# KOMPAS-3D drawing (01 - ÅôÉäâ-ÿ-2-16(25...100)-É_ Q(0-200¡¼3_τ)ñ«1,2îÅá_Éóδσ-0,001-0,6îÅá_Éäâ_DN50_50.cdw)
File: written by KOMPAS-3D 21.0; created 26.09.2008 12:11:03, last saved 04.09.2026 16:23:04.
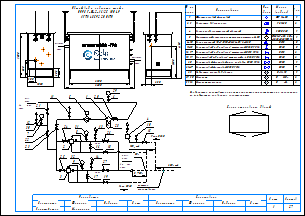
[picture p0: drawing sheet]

Sheets 1-2: A3, landscape

Document properties: Наименование: Макро:21; Автор: RaskoAdmin; Форматы листов документа: 2xA3; Полное имя файла: \\ur38nt01\Departments\КТО\КБ ПУРДГ\Заявки\Прайс-лист на типовые шкафы ГРПШ\ПУРДГ_стандарт_30_04_2026\ПУРДГ с РДГ(Н, В)\ПУРДГ-Ш-2-16(25...100)-Р_ Q(0-200нм3_ч)до1,2МПа_Рвых-0,001-0,6МПа_РДГ_DN50_50.cdw

Title block, sheet 1: Наименование: Пункт учета газа / ПУГ-Ш-400-Р / ЛГТИ.485922.001ТУ; designation: ЛГТИ.03.4411141; sheet number: 1; Количество листов документа: 2; organisation: ООО "ЭЛЬСТЕР Газэлектроника"; Форматы листов документа: A3; stored path: C:\Рабочие документы\Компас\ПУГ\Схема.cdw; Разработал: Устинов; Проверил: Кошкин; Утвердил: Кошкин
Title block, sheet 2: sheet number: 2; stored path: D:\Рабочие документы\Заявки\ПУРДГ\ПУРДГ-ШУЭО-2-100-Р 4411220.cdw; designation, second copy: ЛГТИ.03.4411141-

Views: Вид 1, Вид 2
Referenced files: wcvoit.frw
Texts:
  Normal
  № на
  схеме
  Усл.
  обозн.
  Марка
  (модель)
  Кол.
  Фильтр газовый фланцевый
  ФГ 16-50
  Регулятор давления газа
  РДГ-50
  Клапан предохранительный сбросной
  КПС DN20
  Измерительный комплекс с ротационным счетчиком Ду50
  СГ-ЭК-Р-(0,2...2,0)-
  Кран кнопочный VE-РАСКО-НЗ-1,6-G1/2-М20
  DN15
  Кран шаровой "под приварку" штуцерный DN20 PN16
  DN20
  Кран шаровой "под приварку" штуцерный DN15 PN16
  Кран шаровой "под приварку" штуцерный п/п DN20 PN16
  Кран шаровой фланцевый с мех. приводом DN50 PN16
  Кран шаровой фланцевый DN50 PN16
  DN50
  Индикатор перепада давления
  Манометр
  Манометр-напоромер
  Delta 15
  0...     МПа
  0...     кПа
  Общий вид и габариты шкафа
  ПУРДГ-Ш-2-16(25...100)-Р
  Выход газа
  Вход газа
  logo-rasko-ge.png
  DN 1
  местное
  сопротивление
  Римп DN20
  Выход
  газа
  Р=     кПа
  Вход
  Р=       МПа
  PDI
  Схема открывания дверей
  Предприятие изготовитель может заменять комплектующие на аналогичные,
  не ухудшающие заявленных характеристик.
  Должность
  Конструктор
  Фамилия
  Подпись
  Дата
  Согласовано
  Максимкин
  Лист
  Листов
  POLYLINE_STYLE_0.18_RGB_0_0_0
  POLYLINE_STYLE_0.50_RGB_0_0_0
  POLYLINE_STYLE_0.34_RGB_0_0_0
  PHANTOM_RGB_0_0_0_SC_1_THICK_0.18
  K5LT_THIN_RGB_0_0_0_THICK_0.18
  K5LT32769_RGB_0_0_0_THICK_0.18
  K5LT12_RGB_0_0_0_SC_1_THICK_0.18
  K5LT_DASHED_RGB_0_0_0_SC_1_THICK_0.18
  ACISOTGL_RGB_0_0_0_SC_0.8_THICK_0.25
  CONTINUOUS_RGB_0_127_31_THICK_0.3
  CONTINUOUS_RGB_0_0_255_THICK_0.35
  CONTINUOUS_RGB_255_0_0_THICK_0.35
  POLYLINE_STYLE_0.25_RGB_0_0_0
  CONTINUOUS_RGB_0_0_0_THICK_0.5
  POLYLINE_STYLE_0.35_RGB_0_0_255
  CONTINUOUS_RGB_0_0_0_THICK_0.4
  CONTINUOUS_RGB_0_0_0_THICK_0.35
  НЕВИДИМАЯ_RGB_0_0_0_SC_0.3_THICK_0.25
  СONTINUOUS_RGB_0_0_0_THICK_0.25
  ОСЕВАЯ2_RGB_248_153_30_SC_0.3_THICK_0.25
  Без оформления
Dimensions and other numbers on the sheet: 1; 2, 3; 2; 4; 5; 6-10; 11-15; 16, 17; 18, 19; 20; 21-27; 7; 28; 29, 30; 31, 32; 1500; 250; 300; 1050; 550; 305; 2300; 4130; 2000; 2600; 5,,,7DN 1; 30; 12; 21; 22; 23; 11; 6; 29; 24; 31; 8; 16; 13; 26; 18; 10; 15; 25; 32; 9; 3; 17; 14; 27; 19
